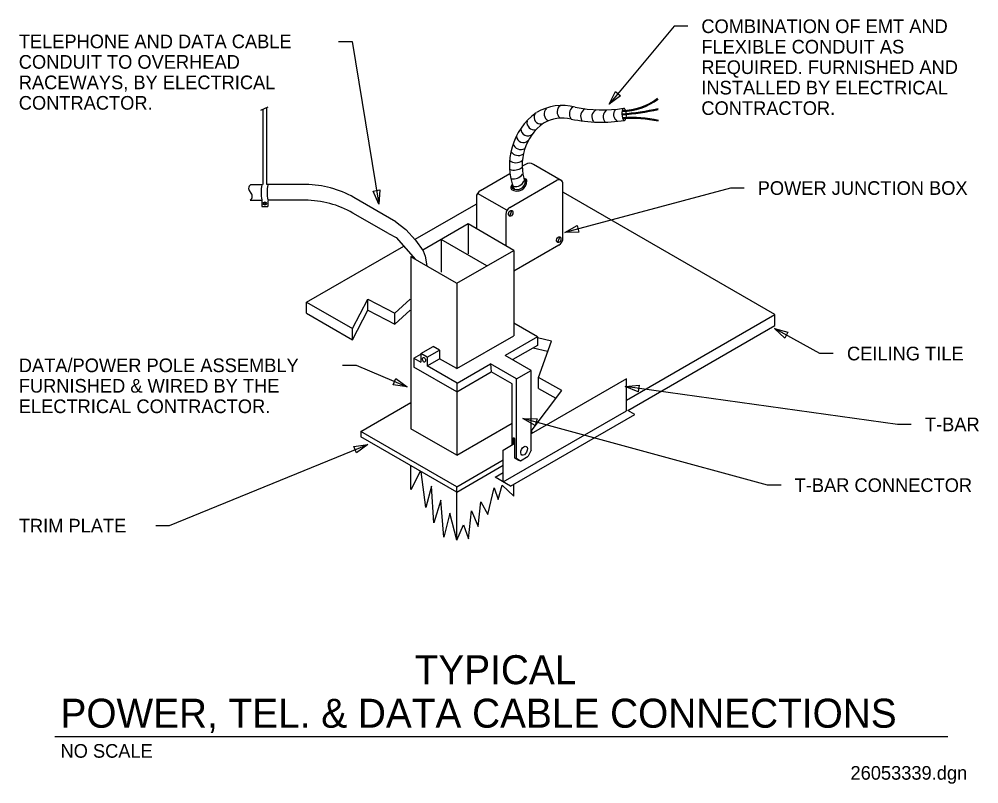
# Model space of a CAD drawing. Extents: x 10312.1 to 10359, y 10110.5 to 10147.8.
import ezdxf

# ---------------------------------------------------------------- set-up
doc = ezdxf.new("R2010")
doc.units = 0
for name, color, linetype in [('G-ANNO-TEXT', 7, 'Continuous'), ('G-DETL-LINE', 7, 'Continuous'), ('G-DETL-OTLN', 7, 'Continuous'), ('G-DETL-PATT', 7, 'Continuous')]:
    doc.layers.add(name, color=color, linetype=linetype)

msp = doc.modelspace()

# ---------------------------------------------------------------- linework, layer by layer
at = {"layer": 'G-ANNO-TEXT'}
for p, q in [((10344.082, 10147.504), (10340.915, 10143.698)), ((10344.748, 10147.504), (10344.082, 10147.504)), ((10327.686, 10146.762), (10328.353, 10146.762)), ((10328.353, 10146.762), (10329.66, 10138.82)), ((10346.832, 10139.6), (10338.748, 10137.434)), ((10347.499, 10139.6), (10346.832, 10139.6)), ((10351.194, 10131.518), (10348.98, 10132.737)), ((10351.861, 10131.518), (10351.194, 10131.518)), ((10327.881, 10130.942), (10328.547, 10130.942)), ((10328.547, 10130.942), (10331.044, 10129.888)), ((10355, 10128.058), (10341.697, 10129.907)), ((10348.638, 10125.089), (10336.702, 10128.341)), ((10355.667, 10128.058), (10355, 10128.058)), ((10319.429, 10123.111), (10329.118, 10127.076)), ((10349.305, 10125.089), (10348.638, 10125.089)), ((10318.762, 10123.111), (10319.429, 10123.111)), ((10313.838, 10112.811), (10357.458, 10112.811))]:
    msp.add_line(p, q, dxfattribs=at)
for points in [[(10341.47, 10144.104), (10340.915, 10143.698), (10341.213, 10144.317)], [(10329.716, 10139.505), (10329.66, 10138.82), (10329.387, 10139.45)], [(10339.435, 10137.446), (10338.748, 10137.434), (10339.349, 10137.768)], [(10349.484, 10132.27), (10348.98, 10132.737), (10349.644, 10132.562)], [(10330.495, 10130.301), (10331.044, 10129.888), (10330.365, 10129.994)], [(10342.335, 10129.65), (10341.697, 10129.907), (10342.381, 10129.98)], [(10337.301, 10128.005), (10336.702, 10128.341), (10337.389, 10128.326)], [(10328.438, 10126.978), (10329.118, 10127.076), (10328.564, 10126.669)]]:
    msp.add_lwpolyline(points, close=True, dxfattribs=at)
at = {"layer": 'G-DETL-LINE'}
for p, q in [((10323.403, 10139.769), (10323.979, 10139.769)), ((10326.095, 10139.769), (10324.185, 10139.769)), ((10323.379, 10139.006), (10323.947, 10139.006)), ((10326.053, 10139.006), (10324.253, 10139.006)), ((10330.496, 10137.954), (10328.439, 10139.141)), ((10330.129, 10137.378), (10328.397, 10138.378)), ((10330.496, 10137.954), (10330.978, 10137.568)), ((10330.978, 10137.568), (10331.445, 10137.053)), ((10330.129, 10137.378), (10330.512, 10137.182)), ((10330.512, 10137.182), (10331.445, 10136.112)), ((10331.445, 10137.053), (10331.83, 10136.537)), ((10331.83, 10136.537), (10331.932, 10136.279)), ((10331.932, 10136.279), (10331.972, 10135.996)), ((10331.972, 10135.996), (10331.999, 10135.792)), ((10331.248, 10124.884), (10331.694, 10125.771))]:
    msp.add_line(p, q, dxfattribs=at)
for points in [[(10333.463, 10122.406), (10333.129, 10123.728), (10332.84, 10122.546), (10332.695, 10124.358), (10332.344, 10123.255), (10332.24, 10125.042), (10331.951, 10123.991), (10331.734, 10125.748)], [(10333.463, 10122.406), (10333.79, 10123.15), (10334.038, 10122.467), (10334.183, 10123.833), (10334.513, 10123.071), (10334.637, 10124.28), (10334.989, 10123.649), (10335.298, 10124.963), (10335.493, 10124.393)], [(10335.493, 10124.393), (10335.684, 10125.087), (10336.253, 10124.555)]]:
    msp.add_lwpolyline(points, dxfattribs=at)
for centre, radius, start, end in [((10338.632, 10141.149), 2.484, 75.6917, 120.7263), ((10338.746, 10143.317), 0.378, 126.6711, 228.4629), ((10339.384, 10143.226), 0.417, 127.5024, 215.1078), ((10340.592, 10149.963), 6.548, 258.1276, 278.9401), ((10341.518, 10146.263), 2.875, 270.568, 307.6341), ((10341.518, 10146.263), 2.924, 270.568, 307.6341), ((10339.204, 10140.719), 3.162, 126.0111, 201.5958), ((10337.574, 10143.063), 0.333, 154.236, 276.3523), ((10338.085, 10143.216), 0.353, 132.4003, 246.9057), ((10339.918, 10143.107), 0.402, 118.1267, 212.4897), ((10340.431, 10143.081), 0.367, 114.9155, 220.436), ((10341.05, 10143.079), 0.431, 131.235, 215.9412), ((10341.525, 10143.196), 0.401, 144.964, 233.9797), ((10340.236, 10157.908), 14.746, 275.1111, 281.9936), ((10340.236, 10157.908), 14.795, 275.1111, 281.9936), ((10339.204, 10140.719), 2.542, 126.0111, 199.4019), ((10337.255, 10142.803), 0.36, 170.934, 278.9708), ((10338.632, 10141.149), 1.869, 76.9642, 119.5657), ((10340.539, 10150.04), 7.224, 258.1276, 278.9401), ((10341.999, 10136.82), 6.228, 77.786, 93.6917), ((10341.999, 10136.82), 6.179, 77.786, 93.6917), ((10336.714, 10142.154), 0.333, 183.9565, 313.9578), ((10336.938, 10142.484), 0.334, 177.5525, 311.6674), ((10336.591, 10141.858), 0.377, 194.4982, 301.7536), ((10336.48, 10141.653), 0.461, 216.7968, 300.1384), ((10336.35, 10141.318), 0.479, 231.5072, 310.2689), ((10336.276, 10141.099), 0.622, 248.836, 307.2409), ((10336.244, 10140.564), 0.519, 257.6557, 326.0024), ((10336.401, 10139.946), 0.491, 237.7675, 0.0961), ((10336.401, 10139.946), 0.421, 237.7675, 0.0961), ((10336.337, 10140.132), 0.455, 256.2995, 339.5212), ((10336.78, 10139.948), 0.113, 350.9916, 104.1616), ((10336.757, 10139.932), 0.065, 6.7883, 81.1998), ((10323.537, 10139.576), 0.235, 124.943, 231.6717), ((10323.246, 10139.207), 0.235, 304.943, 51.6717), ((10326.095, 10135.082), 4.687, 59.9999, 90), ((10336.283, 10139.626), 0.173, 126.1813, 213.444), ((10336.268, 10139.643), 0.101, 135.5493, 216.4077), ((10326.053, 10134.318), 4.687, 60.0001, 90)]:
    msp.add_arc(centre, radius, start, end, dxfattribs=at)
for start_param, end_param in [(5.437822, 10.188453), (4.848374, 5.190828), (4.144016, 4.630896)]:
    msp.add_ellipse((10341.643, 10143.198), major_axis=(-0.018, 0.295), ratio=0.371729, start_param=start_param, end_param=end_param, dxfattribs=at)
for centre, major_axis, ratio in [((10331.869, 10131.211), (-0.039, 0.108), 0.615636), ((10336.757, 10126.769), (0.105, 0.214), 0.575808)]:
    msp.add_ellipse(centre, major_axis=major_axis, ratio=ratio, dxfattribs=at)
at = {"layer": 'G-DETL-OTLN'}
for p, q in [((10323.892, 10143.396), (10324.261, 10143.566)), ((10323.989, 10143.438), (10323.989, 10139.775)), ((10324.182, 10143.509), (10324.182, 10139.775)), ((10336.823, 10140.756), (10336.67, 10140.668)), ((10338.571, 10139.972), (10337.214, 10140.756)), ((10334.62, 10139.484), (10336.057, 10140.314)), ((10336.06, 10138.652), (10338.362, 10139.981)), ((10338.655, 10137.154), (10338.655, 10139.812)), ((10335.913, 10138.512), (10334.486, 10139.336)), ((10323.954, 10139.003), (10323.954, 10138.698)), ((10324.071, 10138.788), (10324.123, 10138.914)), ((10324.24, 10138.996), (10324.24, 10138.698)), ((10334.424, 10139.146), (10334.424, 10137.626)), ((10323.954, 10138.698), (10324.24, 10138.698)), ((10336.054, 10138.234), (10336.154, 10138.508)), ((10335.865, 10138.314), (10335.865, 10136.792)), ((10334.021, 10137.846), (10331.816, 10136.573)), ((10336.252, 10136.558), (10334.021, 10137.846)), ((10334.021, 10137.846), (10334.021, 10136.393)), ((10334.937, 10135.799), (10332.706, 10137.087)), ((10332.706, 10137.087), (10332.706, 10135.486)), ((10338.401, 10136.945), (10338.501, 10137.219)), ((10333.463, 10134.948), (10336.253, 10136.558)), ((10336.253, 10136.558), (10336.253, 10132.389)), ((10338.46, 10136.816), (10336.259, 10135.545)), ((10331.231, 10136.235), (10331.302, 10136.276)), ((10333.462, 10134.947), (10331.231, 10136.235)), ((10331.231, 10136.235), (10331.231, 10127.848)), ((10333.463, 10134.948), (10333.463, 10130.779)), ((10337.406, 10132.336), (10336.253, 10133.001)), ((10333.463, 10130.779), (10336.253, 10132.389)), ((10337.406, 10132.336), (10335.835, 10131.429)), ((10337.406, 10132.336), (10337.406, 10131.916)), ((10331.719, 10131.518), (10332.319, 10131.865)), ((10332.629, 10131.686), (10332.319, 10131.865)), ((10337.406, 10131.916), (10336.199, 10131.219)), ((10331.373, 10131.292), (10331.719, 10131.492)), ((10332.028, 10131.339), (10331.719, 10131.518)), ((10331.719, 10131.518), (10331.719, 10131.093)), ((10332.028, 10131.339), (10332.629, 10131.686)), ((10332.028, 10131.339), (10332.028, 10130.914)), ((10332.629, 10131.686), (10332.629, 10131.26)), ((10337.106, 10130.695), (10335.835, 10131.429)), ((10331.373, 10131.292), (10331.373, 10130.846)), ((10331.373, 10131.292), (10331.719, 10131.093)), ((10332.028, 10130.914), (10332.629, 10131.26)), ((10333.485, 10130.073), (10332.028, 10130.914)), ((10333.463, 10130.779), (10332.629, 10131.26)), ((10333.485, 10130.073), (10335.119, 10131.016)), ((10336.39, 10130.282), (10335.119, 10131.016)), ((10335.119, 10131.016), (10335.155, 10130.617)), ((10333.463, 10129.64), (10331.373, 10130.846)), ((10333.463, 10129.64), (10335.155, 10130.617)), ((10336.168, 10130.032), (10335.155, 10130.617)), ((10336.39, 10130.282), (10337.106, 10130.695)), ((10337.106, 10126.8), (10337.106, 10130.695)), ((10333.463, 10130.073), (10333.463, 10126.559)), ((10336.168, 10127.051), (10336.168, 10130.032)), ((10336.39, 10126.401), (10336.39, 10130.282)), ((10341.753, 10130.276), (10337.106, 10127.593)), ((10341.753, 10128.723), (10341.753, 10130.276)), ((10328.784, 10127.714), (10331.231, 10129.127)), ((10335.729, 10125.244), (10341.753, 10128.723)), ((10336.093, 10125.041), (10342.161, 10128.544)), ((10342.161, 10128.544), (10341.824, 10128.738)), ((10333.463, 10126.559), (10336.168, 10128.121)), ((10333.463, 10125.013), (10328.784, 10127.714)), ((10328.784, 10127.714), (10328.784, 10127.451)), ((10333.463, 10126.559), (10331.231, 10127.848)), ((10333.463, 10124.749), (10328.784, 10127.451)), ((10335.729, 10126.798), (10336.311, 10127.134)), ((10336.311, 10127.357), (10336.239, 10127.399)), ((10336.239, 10127.092), (10336.239, 10127.399)), ((10336.311, 10126.403), (10336.311, 10127.357)), ((10335.729, 10125.244), (10335.729, 10126.798)), ((10337.106, 10126.8), (10336.96, 10126.5)), ((10333.463, 10125.013), (10335.729, 10126.322)), ((10336.311, 10126.403), (10336.51, 10126.287)), ((10336.311, 10126.403), (10336.39, 10126.401)), ((10336.39, 10126.401), (10336.588, 10126.285)), ((10336.588, 10126.285), (10336.51, 10126.287)), ((10336.588, 10126.285), (10336.96, 10126.5)), ((10331.231, 10124.884), (10331.231, 10126.038)), ((10333.463, 10124.749), (10335.729, 10126.058)), ((10335.34, 10125.476), (10335.729, 10125.701)), ((10336.093, 10125.041), (10335.34, 10125.476)), ((10333.463, 10122.406), (10333.463, 10125.013)), ((10336.253, 10124.555), (10336.253, 10125.133))]:
    msp.add_line(p, q, dxfattribs=at)
msp.add_circle((10324.094, 10138.847), 0.0755, dxfattribs=at)
for centre, radius, start, end in [((10337.018, 10140.418), 0.391, 60.0008, 119.9998), ((10338.46, 10139.812), 0.195, 0.0025, 120.0004), ((10325.611, 10139.386), 1.704, 167.4851, 192.5149), ((10325.903, 10139.386), 1.704, 167.4851, 192.5149), ((10334.815, 10139.146), 0.391, 119.9988, 180), ((10336.255, 10138.314), 0.391, 119.9994, 180), ((10338.264, 10137.154), 0.391, 299.9999, 360)]:
    msp.add_arc(centre, radius, start, end, dxfattribs=at)
for centre in [(10336.102, 10138.371), (10338.449, 10137.082)]:
    msp.add_ellipse(centre, major_axis=(0.052, 0.137), ratio=0.70625, dxfattribs=at)
at = {"layer": 'G-DETL-PATT'}
for p, q in [((10348.996, 10133.42), (10338.679, 10139.376)), ((10334.399, 10138.799), (10331.421, 10137.08)), ((10326.131, 10134.026), (10330.875, 10136.765)), ((10329.12, 10133.632), (10329.12, 10134.174)), ((10326.131, 10134.026), (10328.368, 10132.734)), ((10326.131, 10133.484), (10326.131, 10134.026)), ((10326.131, 10133.484), (10328.368, 10132.193)), ((10328.368, 10132.193), (10329.12, 10133.632)), ((10329.12, 10133.632), (10330.444, 10132.95)), ((10330.444, 10132.95), (10331.196, 10133.632)), ((10330.444, 10132.95), (10330.444, 10133.491)), ((10341.753, 10129.239), (10348.996, 10133.42)), ((10348.996, 10132.879), (10348.996, 10133.42)), ((10341.824, 10128.738), (10348.996, 10132.879)), ((10328.368, 10132.193), (10328.368, 10132.734)), ((10337.196, 10131.795), (10337.898, 10131.638)), ((10337.458, 10129.818), (10337.458, 10130.352)), ((10337.458, 10129.818), (10338.314, 10129.342)), ((10337.189, 10127.641), (10337.106, 10127.689))]:
    msp.add_line(p, q, dxfattribs=at)
for points in [[(10328.368, 10132.734), (10329.12, 10134.174), (10330.444, 10133.491), (10331.196, 10134.174)], [(10337.106, 10127.725), (10338.603, 10129.715), (10337.458, 10130.352), (10338.102, 10132.126), (10337.406, 10132.283)]]:
    msp.add_lwpolyline(points, dxfattribs=at)

# ---------------------------------------------------------------- texts
at = {"layer": 'G-ANNO-TEXT'}
for s, height, p in [('COMBINATION OF EMT AND', 0.66667, (10345.415, 10147.17)), ('TELEPHONE AND DATA CABLE', 0.66667, (10312.075, 10146.428)), ('FLEXIBLE CONDUIT AS', 0.66667, (10345.415, 10146.17)), ('CONDUIT TO OVERHEAD', 0.66667, (10312.075, 10145.428)), ('REQUIRED. FURNISHED AND', 0.66667, (10345.415, 10145.17)), ('RACEWAYS, BY ELECTRICAL', 0.66667, (10312.075, 10144.428)), ('INSTALLED BY ELECTRICAL', 0.66667, (10345.415, 10144.17)), ('CONTRACTOR.', 0.66667, (10312.075, 10143.428)), ('CONTRACTOR.', 0.66667, (10345.415, 10143.17)), ('POWER JUNCTION BOX', 0.66667, (10348.166, 10139.267)), ('CEILING TILE', 0.66667, (10352.528, 10131.185)), ('DATA/POWER POLE ASSEMBLY', 0.66667, (10312.075, 10130.608)), ('FURNISHED & WIRED BY THE', 0.66667, (10312.075, 10129.608)), ('ELECTRICAL CONTRACTOR.', 0.66667, (10312.075, 10128.608)), ('T-BAR', 0.6667, (10356.334, 10127.724)), ('T-BAR CONNECTOR', 0.66667, (10349.971, 10124.756)), ('TRIM PLATE', 0.6667, (10312.075, 10122.778)), ('TYPICAL', 1.4167, (10331.413, 10115.368)), ('POWER, TEL. & DATA CABLE CONNECTIONS', 1.41667, (10314.112, 10113.243)), ('NO SCALE', 0.6667, (10314.112, 10111.776)), ('26053339.dgn', 0.66667, (10352.699, 10110.704))]:
    msp.add_text(s, height=height, dxfattribs=at).set_placement(p)

doc.saveas('drawing.dxf')
